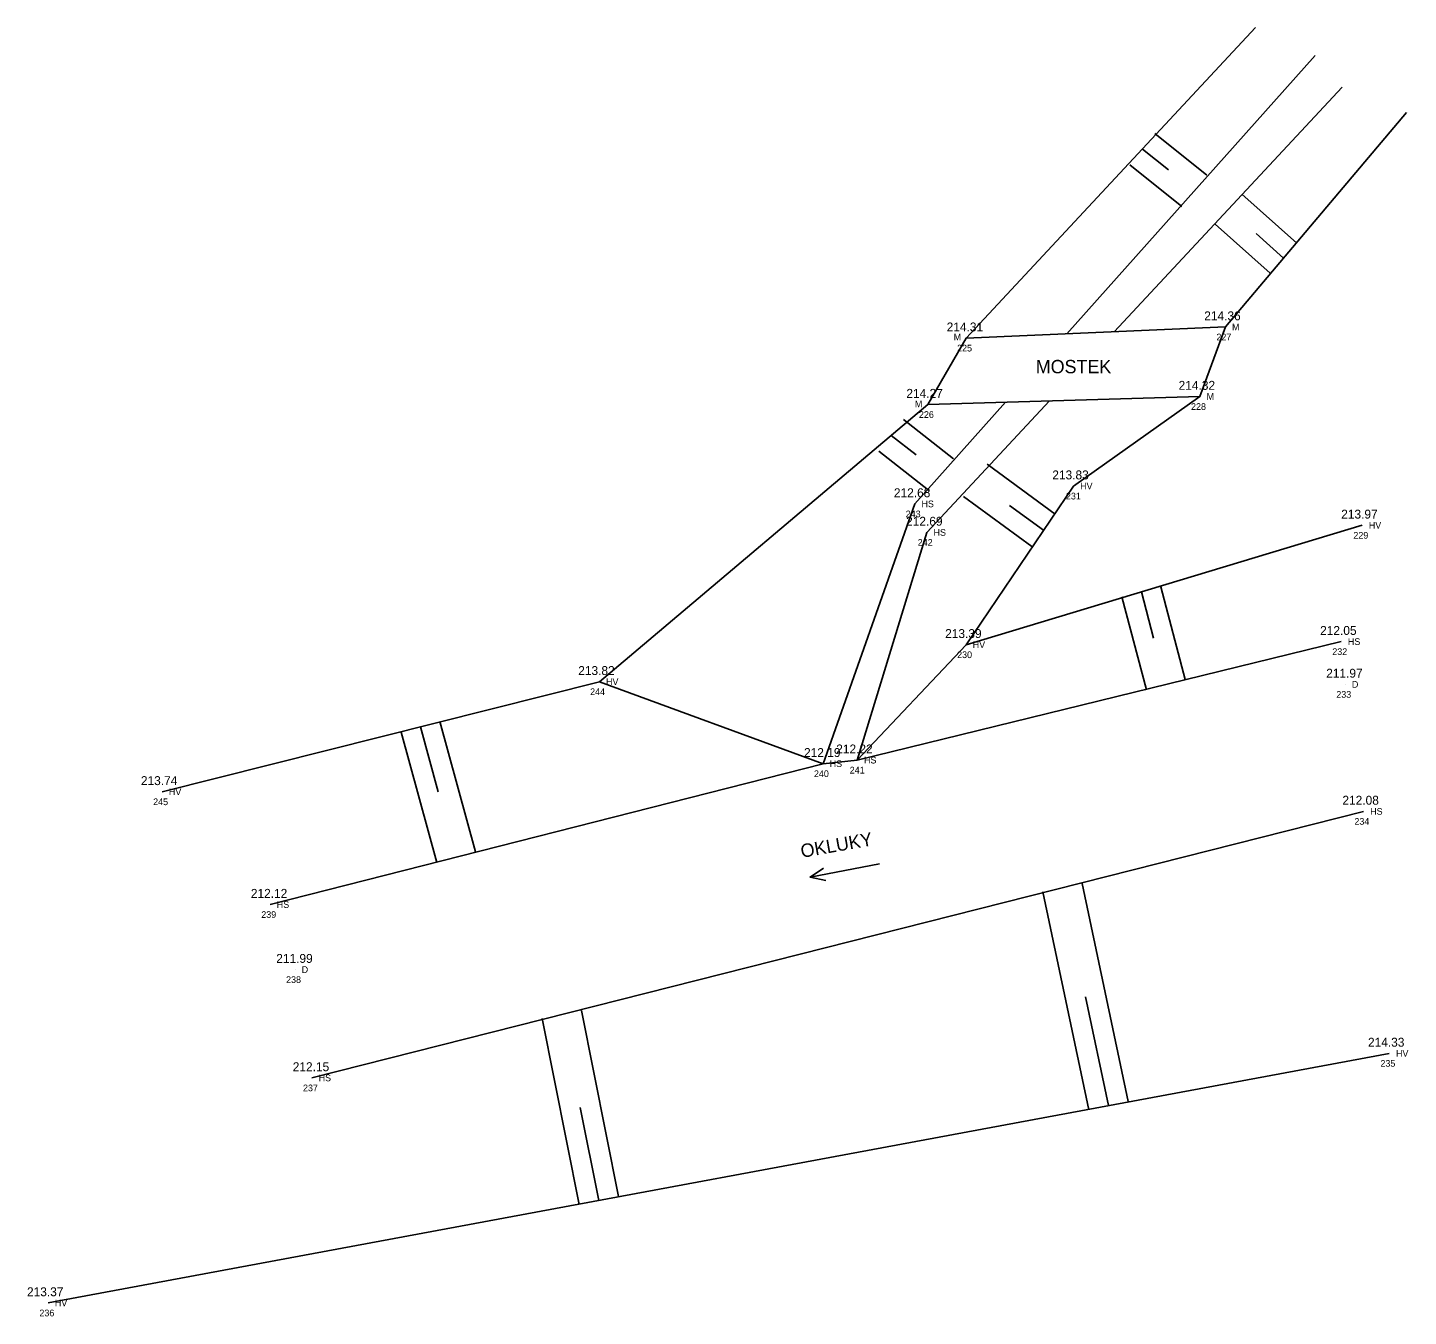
# Model space of a CAD drawing. Extents: x -534428 to -534317, y -1190536 to -1189619.
# Drawn here: x -534428.15 to -534397.16, y -1190536.37 to -1190507.45 of the extents above; entities that cross this region are included whole.
import ezdxf

# ---------------------------------------------------------------- set-up
doc = ezdxf.new("R2010")
doc.units = 0
for name, color, linetype in [('Definiční bod kú', 7, 'Continuous'), ('Vnitřní kresba', 7, 'Continuous'), ('Vrstva 22', 7, 'Continuous'), ('Vrstva 24', 7, 'Continuous'), ('Vrstva 35', 7, 'Continuous'), ('Vrstva 60', 7, 'Continuous'), ('Vrstva 61', 7, 'Continuous')]:
    doc.layers.add(name, color=color, linetype=linetype)

msp = doc.modelspace()

# ---------------------------------------------------------------- linework, layer by layer
at = {"layer": 'Definiční bod kú'}
for points in [[(-534409.032, -1190526.217), (-534410.59, -1190526.515), (-534410.239, -1190526.592)], [(-534409.032, -1190526.217), (-534410.59, -1190526.515), (-534410.292, -1190526.313)]]:
    msp.add_lwpolyline(points, dxfattribs=at)
at = {"layer": 'Vnitřní kresba'}
msp.add_lwpolyline([(-534407.95, -1190515.91), (-534401.84, -1190515.73), (-534401.27, -1190514.17), (-534407.09, -1190514.42)], close=True, dxfattribs=at)
at = {"layer": 'Vrstva 35'}
for p, q in [((-534407.09, -1190514.42), (-534407.09, -1190514.42)), ((-534401.27, -1190514.17), (-534401.27, -1190514.17)), ((-534407.95, -1190515.91), (-534407.95, -1190515.91)), ((-534401.84, -1190515.73), (-534401.84, -1190515.73)), ((-534404.68, -1190517.74), (-534404.68, -1190517.74)), ((-534408.24, -1190518.14), (-534408.24, -1190518.14)), ((-534407.97, -1190518.78), (-534407.97, -1190518.78)), ((-534398.2, -1190518.62), (-534398.2, -1190518.62)), ((-534398.67, -1190521.23), (-534398.67, -1190521.23)), ((-534407.09, -1190521.3), (-534407.09, -1190521.3)), ((-534415.32, -1190522.13), (-534415.32, -1190522.13)), ((-534398.58, -1190522.19), (-534398.58, -1190522.19)), ((-534410.3, -1190523.97), (-534410.3, -1190523.97)), ((-534409.53, -1190523.89), (-534409.53, -1190523.89)), ((-534425.13, -1190524.6), (-534425.13, -1190524.6)), ((-534398.17, -1190525.04), (-534398.17, -1190525.04)), ((-534422.71, -1190527.13), (-534422.71, -1190527.13)), ((-534422.15, -1190528.59), (-534422.15, -1190528.59)), ((-534397.59, -1190530.47), (-534397.59, -1190530.47)), ((-534421.77, -1190531.02), (-534421.77, -1190531.02)), ((-534427.69, -1190536.07), (-534427.69, -1190536.07))]:
    msp.add_line(p, q, dxfattribs=at)
at = {"layer": 'Vrstva 60'}
for p, q in [((-534407.09, -1190514.42), (-534400.591, -1190507.452)), ((-534404.83, -1190514.323), (-534399.254, -1190508.08)), ((-534403.767, -1190514.277), (-534398.646, -1190508.791)), ((-534401.27, -1190514.17), (-534397.206, -1190509.36)), ((-534415.32, -1190522.13), (-534407.95, -1190515.91)), ((-534408.24, -1190518.14), (-534406.202, -1190515.859)), ((-534407.97, -1190518.78), (-534405.216, -1190515.829)), ((-534404.68, -1190517.74), (-534401.84, -1190515.73)), ((-534407.09, -1190521.3), (-534404.68, -1190517.74)), ((-534410.3, -1190523.97), (-534408.24, -1190518.14)), ((-534409.53, -1190523.89), (-534407.97, -1190518.78)), ((-534398.2, -1190518.62), (-534407.09, -1190521.3)), ((-534409.53, -1190523.89), (-534407.09, -1190521.3)), ((-534425.13, -1190524.6), (-534415.32, -1190522.13)), ((-534415.32, -1190522.13), (-534410.3, -1190523.97)), ((-534421.77, -1190531.02), (-534398.17, -1190525.04)), ((-534427.69, -1190536.07), (-534397.59, -1190530.47))]:
    msp.add_line(p, q, dxfattribs=at)
msp.add_lwpolyline([(-534422.71, -1190527.13), (-534410.3, -1190523.97), (-534409.53, -1190523.89), (-534398.67, -1190521.23)], dxfattribs=at)
at = {"layer": 'Vrstva 61'}
for p, q in [((-534402.852, -1190509.826), (-534401.682, -1190510.762)), ((-534403.133, -1190510.178), (-534402.548, -1190510.645)), ((-534403.414, -1190510.529), (-534402.244, -1190511.464)), ((-534399.665, -1190512.289), (-534400.899, -1190511.19)), ((-534400.264, -1190512.961), (-534401.498, -1190511.862)), ((-534399.965, -1190512.625), (-534400.582, -1190512.075)), ((-534408.492, -1190516.248), (-534407.373, -1190517.127)), ((-534408.77, -1190516.602), (-534408.211, -1190517.042)), ((-534409.048, -1190516.956), (-534407.93, -1190517.835)), ((-534405.086, -1190518.368), (-534406.616, -1190517.251)), ((-534405.617, -1190519.095), (-534407.147, -1190517.977)), ((-534405.351, -1190518.731), (-534406.116, -1190518.173)), ((-534402.72, -1190519.999), (-534402.172, -1190522.08)), ((-534403.59, -1190520.228), (-534403.043, -1190522.309)), ((-534403.155, -1190520.114), (-534402.881, -1190521.154)), ((-534419.336, -1190523.141), (-534418.934, -1190524.604)), ((-534418.902, -1190523.022), (-534418.098, -1190525.947)), ((-534419.77, -1190523.261), (-534418.966, -1190526.185)), ((-534404.335, -1190531.736), (-534405.368, -1190526.845)), ((-534403.454, -1190531.55), (-534404.487, -1190526.659)), ((-534403.895, -1190531.643), (-534404.411, -1190529.198)), ((-534414.893, -1190533.684), (-534415.721, -1190529.511)), ((-534415.776, -1190533.859), (-534416.603, -1190529.687)), ((-534415.334, -1190533.771), (-534415.748, -1190531.685))]:
    msp.add_line(p, q, dxfattribs=at)

# ---------------------------------------------------------------- texts
at = {"layer": 'Definiční bod kú'}
for s, height, p in [('214.36', 0.2, (-534401.744, -1190514.02)), ('214.31', 0.2, (-534407.525, -1190514.27)), ('MOSTEK', 0.3, (-534405.525, -1190515.209)), ('214.32', 0.2, (-534402.319, -1190515.58)), ('214.27', 0.2, (-534408.429, -1190515.76)), ('213.83', 0.2, (-534405.154, -1190517.59)), ('212.68', 0.2, (-534408.709, -1190517.99)), ('212.69', 0.2, (-534408.435, -1190518.63)), ('213.97', 0.2, (-534398.67, -1190518.47)), ('213.39', 0.2, (-534407.559, -1190521.15)), ('212.05', 0.2, (-534399.143, -1190521.08)), ('213.82', 0.2, (-534415.794, -1190521.98)), ('211.97', 0.2, (-534399.007, -1190522.04)), ('212.19', 0.2, (-534410.726, -1190523.82)), ('212.22', 0.2, (-534410.004, -1190523.74)), ('213.74', 0.2, (-534425.609, -1190524.45)), ('212.08', 0.2, (-534398.643, -1190524.89)), ('212.12', 0.2, (-534423.141, -1190526.98)), ('211.99', 0.2, (-534422.571, -1190528.44)), ('214.33', 0.2, (-534398.069, -1190530.32)), ('212.15', 0.2, (-534422.201, -1190530.87)), ('213.37', 0.2, (-534428.165, -1190535.92))]:
    msp.add_text(s, height=height, dxfattribs=at).set_placement(p)
msp.add_text('OKLUKY', height=0.3, rotation=10.0375, dxfattribs=at).set_placement((-534410.774, -1190526.084))
at = {"layer": 'Vrstva 22'}
for s, p in [('227', (-534401.471, -1190514.47)), ('225', (-534407.29, -1190514.72)), ('228', (-534402.04, -1190516.03)), ('226', (-534408.147, -1190516.21)), ('231', (-534404.848, -1190518.04)), ('243', (-534408.444, -1190518.44)), ('229', (-534398.397, -1190518.92)), ('242', (-534408.174, -1190519.08)), ('230', (-534407.29, -1190521.6)), ('232', (-534398.87, -1190521.53)), ('244', (-534415.527, -1190522.43)), ('233', (-534398.78, -1190522.49)), ('241', (-534409.701, -1190524.19)), ('240', (-534410.503, -1190524.27)), ('245', (-534425.334, -1190524.9)), ('234', (-534398.374, -1190525.34)), ('239', (-534422.907, -1190527.43)), ('238', (-534422.35, -1190528.89)), ('235', (-534397.79, -1190530.77)), ('237', (-534421.971, -1190531.32)), ('236', (-534427.887, -1190536.37))]:
    msp.add_text(s, height=0.15, dxfattribs=at).set_placement(p)
at = {"layer": 'Vrstva 24'}
for s, p in [('M', (-534401.12, -1190514.245)), ('M', (-534407.367, -1190514.47)), ('M', (-534401.69, -1190515.805)), ('M', (-534408.238, -1190515.973)), ('HV', (-534404.53, -1190517.815)), ('HS', (-534408.09, -1190518.215)), ('HS', (-534407.82, -1190518.855)), ('HV', (-534398.05, -1190518.695)), ('HV', (-534406.94, -1190521.375)), ('HS', (-534398.52, -1190521.305)), ('HV', (-534415.17, -1190522.205)), ('D', (-534398.43, -1190522.265)), ('HS', (-534410.15, -1190524.045)), ('HS', (-534409.38, -1190523.965)), ('HV', (-534424.98, -1190524.675)), ('HS', (-534398.02, -1190525.115)), ('HS', (-534422.56, -1190527.205)), ('D', (-534422, -1190528.665)), ('HV', (-534397.44, -1190530.545)), ('HS', (-534421.62, -1190531.095)), ('HV', (-534427.54, -1190536.145))]:
    msp.add_text(s, height=0.15, dxfattribs=at).set_placement(p)

doc.saveas('drawing.dxf')
